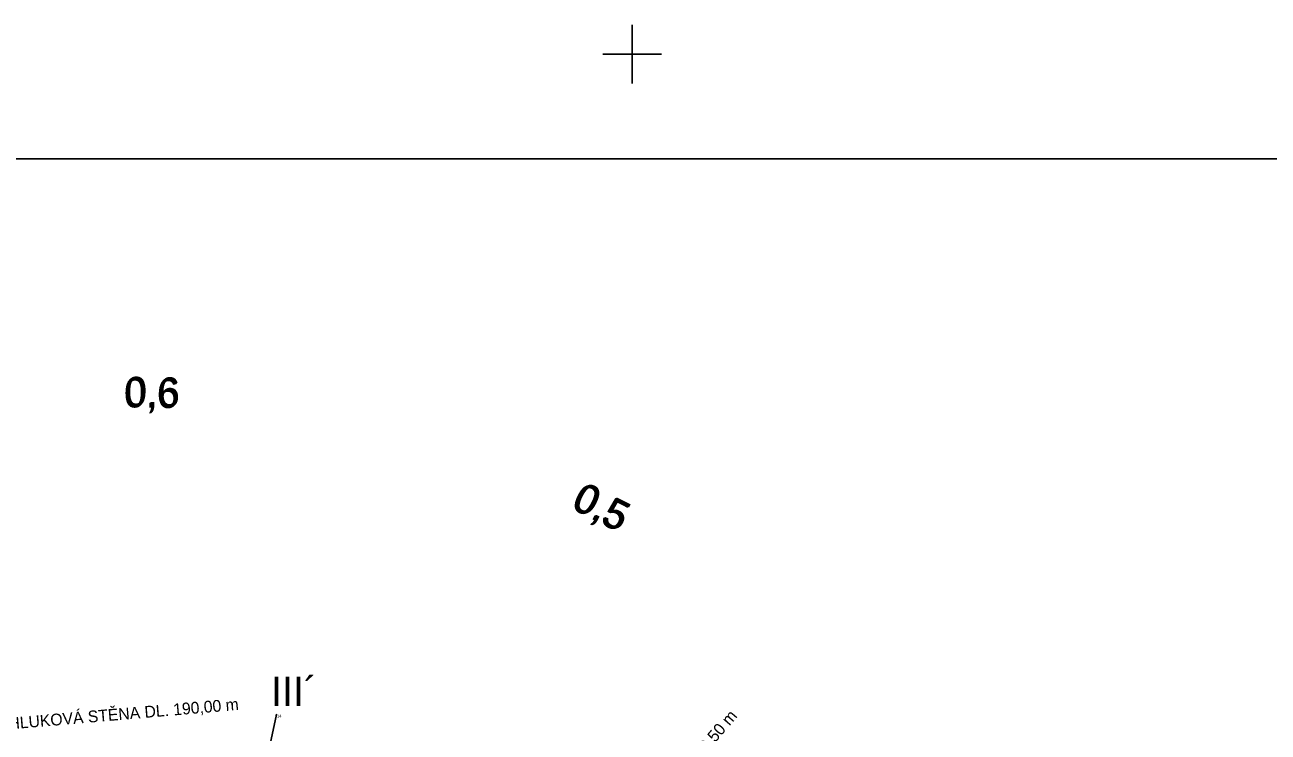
# Model space of a CAD drawing. Extents: x -606444 to -604546, y -1158114 to -1156869.
# Drawn here: x -605380.6 to -604958.2, y -1157109.2 to -1156868.7 of the extents above; entities that cross this region are included whole.
import ezdxf

# ---------------------------------------------------------------- set-up
doc = ezdxf.new("R2010")
doc.units = 0
for name, color, linetype in [('FORMAT', 7, 'Continuous'), ('NS_VB_POP', 7, 'Continuous'), ('OSAPOP', 7, 'Continuous'), ('ramecek_tisk', 7, 'Continuous'), ('stabilitní profily_předběžný GTP', 7, 'Continuous')]:
    doc.layers.add(name, color=color, linetype=linetype)

msp = doc.modelspace()

# ---------------------------------------------------------------- linework, layer by layer
for q in [(-605295.26, -1157103.17), (-605295.26, -1157103.37), (-605295.06, -1157103.17), (-605295.06, -1157103.37)]:
    msp.add_line((-605295.16, -1157103.27), q)
at = {"layer": 'FORMAT'}
for p, q in [((-605174.31, -1156888.73), (-605174.31, -1156868.73)), ((-605184.31, -1156878.73), (-605164.31, -1156878.73))]:
    msp.add_line(p, q, dxfattribs=at)
at = {"layer": 'ramecek_tisk'}
msp.add_line((-606362.25, -1156914.34), (-604562.25, -1156914.34), dxfattribs=at)
at = {"layer": 'stabilitní profily_předběžný GTP'}
msp.add_lwpolyline([(-605304.56, -1157147.37), (-605295.16, -1157103.27)], dxfattribs=at)

# ---------------------------------------------------------------- texts
msp.add_text('114', height=1).set_placement((-605295.77, -1157104.27))
at = {"layer": 'NS_VB_POP'}
for s, rotation, p in [('NÍZKÁ PROTIHLUKOVÁ STĚNA DL. 190,00 m', 4.8613, (-605419.5, -1157111.16)), ('MOST DL. 13,50 m', 49.4418, (-605168.3, -1157138.88))]:
    msp.add_text(s, height=4, rotation=rotation, dxfattribs=at).set_placement(p)
at = {"layer": 'OSAPOP'}
for s, rotation, p in [('0,6', 359.0973, (-605347.06, -1156998.78)), ('0,6', 359.0973, (-605346.91, -1156998.63)), ('0,6', 359.0973, (-605346.76, -1156998.48)), ('0,6', 359.0973, (-605346.61, -1156998.34)), ('0,5', 333.0538, (-605195.53, -1157032.98)), ('0,5', 333.0538, (-605195.33, -1157032.92)), ('0,5', 333.0538, (-605195.13, -1157032.85)), ('0,5', 333.0538, (-605194.93, -1157032.78))]:
    msp.add_text(s, height=10, rotation=rotation, dxfattribs=at).set_placement(p)
at = {"layer": 'stabilitní profily_předběžný GTP'}
msp.add_text('III´', height=10, dxfattribs=at).set_placement((-605296.97, -1157100.34))

doc.saveas('drawing.dxf')
